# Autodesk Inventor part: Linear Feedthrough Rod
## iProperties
Shininess: 64.0
Length Units: 11272
Angle Units: 11279
Time Units: 11290
Mass Units: 11286
Length Display Precision: 3
Angle Display Precision: 2
Compacted: True
Part Number: Linear Feedthrough Rod
Document SubType Name: Modeling
Created: 2004-04
Designer: jpittman
Manufacturer: Standard
Standards Organization: Custom
Density: 0.0
Volumn: 0.0
Area: 0.0
PropertySet Name: Model Information
Control State: 0
Master: False
Checked Out: False
Author: jpittman
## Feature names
1. Extrusion1
2. Extrusion2
3. Hole1
